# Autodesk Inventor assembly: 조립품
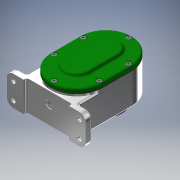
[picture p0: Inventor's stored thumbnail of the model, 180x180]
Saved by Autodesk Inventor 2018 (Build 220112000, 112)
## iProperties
Created: 2021-05
Part Number: 조립품
Material: 일반
Document SubType Name: Assembly
Designer: Admin
Author: Admin
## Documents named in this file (19)
- C:\Users\Admin\Desktop\710509V1008\조립품.iam
- C:\Users\Admin\Desktop\710509V1008\본체.ipt
- C:\Users\Admin\Desktop\710509V1008\축 A.ipt
- C:\Users\Admin\Desktop\710509V1008\베어링 6001.ipt
- 베어링 6001.ipt
- C:\Users\Admin\Desktop\710509V1008\커버 A.ipt
- C:\Users\Admin\Desktop\710509V1008\베어링 6002.ipt
- 베어링 6002.ipt
- C:\Users\Admin\Desktop\710509V1008\칼라.ipt
- C:\Users\Admin\Desktop\710509V1008\축 B.ipt
- C:\Users\Admin\Desktop\710509V1008\키 5 x 5 x 12.ipt
- C:\Users\Admin\Desktop\710509V1008\키 4 x 4 x 12.ipt
- C:\Users\Admin\Desktop\710509V1008\개스킷 A.ipt
- C:\Users\Admin\Desktop\710509V1008\스퍼기어 A.ipt
- C:\Users\Admin\Desktop\710509V1008\스퍼기어 B.ipt
- C:\Users\Admin\Desktop\710509V1008\개스킷 B.ipt
- C:\Users\Admin\Desktop\710509V1008\커버 B.ipt
- C:\Users\Admin\Desktop\710509V1008\오일 실 12 22 7.ipt
- C:\Users\Admin\Desktop\710509V1008\볼트 M4.ipt
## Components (2 placed, 2 different names)
1. 개스킷 A:1
2. 개스킷 B:1
